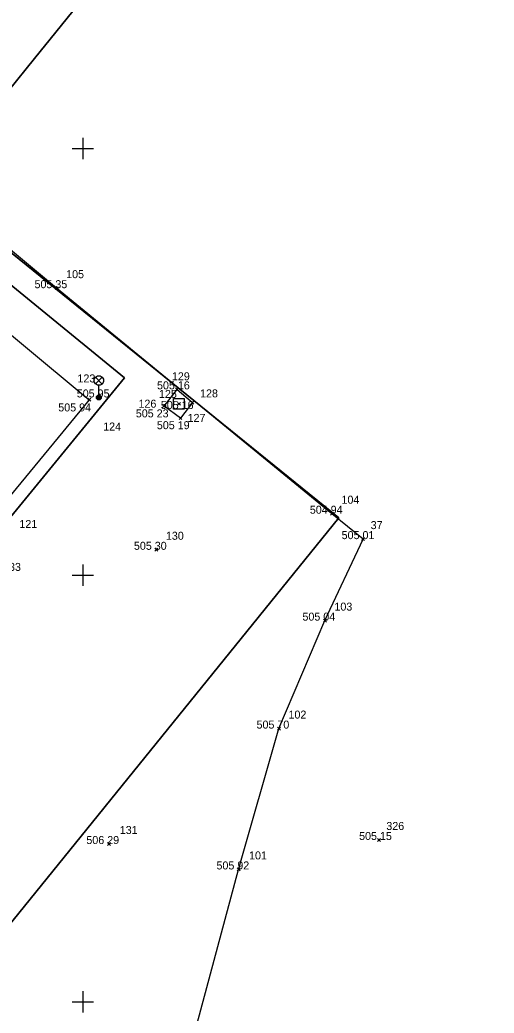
# Model space of a CAD drawing. Extents: x -408550 to -407654, y -1233019 to -1231230.
# Drawn here: x -407922.95 to -407900.75, y -1232060.52 to -1232013.97 of the extents above; entities that cross this region are included whole.
import ezdxf

# ---------------------------------------------------------------- set-up
doc = ezdxf.new("R2010")
doc.units = 0
for name, color, linetype in [('Level 1', 7, 'Continuous'), ('Level 12', 7, 'Continuous'), ('Level 16', 7, 'Continuous'), ('Level 20', 7, 'Continuous'), ('Level 23', 7, 'Continuous'), ('Level 26', 7, 'Continuous'), ('Level 40', 7, 'Continuous'), ('Level 45', 7, 'Continuous')]:
    doc.layers.add(name, color=color, linetype=linetype)

msp = doc.modelspace()

# ---------------------------------------------------------------- linework, layer by layer
at = {"layer": 'Level 1'}
for p, q in [((-407920, -1232019.5), (-407920, -1232020.5)), ((-407920.5, -1232020), (-407919.5, -1232020)), ((-407920, -1232039.5), (-407920, -1232040.5)), ((-407920.5, -1232040), (-407919.5, -1232040)), ((-407920, -1232059.5), (-407920, -1232060.5)), ((-407920.5, -1232060), (-407919.5, -1232060))]:
    msp.add_line(p, q, dxfattribs=at)
for points in [[(-408002.95, -1231959.78), (-407998.58, -1231963.3), (-407985.37, -1231974.5), (-407975.08, -1231982.73), (-407972.21, -1231984.54), (-407969.45, -1231986.76), (-407966.11, -1231989.44), (-407955.64, -1231997.88), (-407939.09, -1232011.47), (-407927.08, -1232021.88), (-407908.02, -1232037.31)], [(-407865.11, -1232098.76), (-407959.41, -1232100.85), (-407908.02, -1232037.31), (-407927.08, -1232021.88), (-407925.98, -1232020.38), (-407922.27, -1232015.79), (-407913.48, -1232004.91), (-407905.89, -1231995.51), (-407896.46, -1231983.85)], [(-407908.02, -1232037.31), (-407959.41, -1232100.85), (-407964.75, -1232098.99), (-407974.67, -1232095.53), (-407985.8, -1232091.65), (-408004.8, -1232085.03), (-408023.96, -1232078.34), (-408035.27, -1232074.4), (-408044.77, -1232071.09)]]:
    msp.add_lwpolyline(points, dxfattribs=at)
for points in [[(-407908.98, -1231973.85), (-407908.6, -1231973.38), (-407908.02, -1231973.41), (-407904.44, -1231976.23), (-407900.26, -1231979.53), (-407895.94, -1231983.2), (-407896.46, -1231983.85), (-407905.89, -1231995.51), (-407913.48, -1232004.91), (-407922.27, -1232015.79), (-407925.98, -1232020.38), (-407927.08, -1232021.88), (-407939.09, -1232011.47)], [(-407945.9, -1232007.95), (-407918.05, -1232030.75), (-407931.35, -1232047), (-407959.2, -1232024.19)], [(-407918.05, -1232030.75), (-407945.9, -1232007.95), (-407959.2, -1232024.19), (-407931.35, -1232047)]]:
    msp.add_lwpolyline(points, close=True, dxfattribs=at)
at = {"layer": 'Level 12'}
msp.add_lwpolyline([(-408056.73, -1232038.31), (-408035.18, -1232049.43), (-408016.67, -1232058.98), (-407995.64, -1232070.23), (-407983.94, -1232082.87), (-407968.55, -1232099.65), (-407955.47, -1232103.17), (-407935.56, -1232108.32), (-407927.78, -1232110.15), (-407922.43, -1232090.45), (-407918.07, -1232073.76), (-407912.71, -1232053.79), (-407910.82, -1232047.19), (-407908.67, -1232042.13), (-407906.88, -1232038.31), (-407908.34, -1232037.12), (-407921.23, -1232026.55), (-407939.09, -1232011.64)], dxfattribs=at)
at = {"layer": 'Level 16'}
for points in [[(-407919.7, -1232031.78), (-407924.37, -1232037.43), (-407923.48, -1232038.26), (-407925.54, -1232040.73), (-407926.5, -1232040), (-407931.46, -1232045.69), (-407956.75, -1232024.26), (-407952.09, -1232018.67), (-407953, -1232017.86), (-407950.95, -1232015.4), (-407949.93, -1232016.06), (-407945.35, -1232010.41)], [(-407914.87, -1232031.91), (-407915.43, -1232032.64), (-407916.2, -1232032.08), (-407915.59, -1232031.29)]]:
    msp.add_lwpolyline(points, close=True, dxfattribs=at)
at = {"layer": 'Level 20'}
msp.add_lwpolyline([(-407915.75, -1232031.72), (-407915.25, -1232031.72), (-407915.25, -1232032.22), (-407915.75, -1232032.22)], close=True, dxfattribs=at)
at = {"layer": 'Level 23'}
for points in [[(-407921.161, -1232026.619), (-407921.299, -1232026.481)], [(-407921.299, -1232026.619), (-407921.161, -1232026.481)], [(-407915.521, -1232031.359), (-407915.659, -1232031.221)], [(-407915.659, -1232031.359), (-407915.521, -1232031.221)], [(-407919.631, -1232031.849), (-407919.769, -1232031.711)], [(-407919.769, -1232031.849), (-407919.631, -1232031.711)], [(-407919.181, -1232031.739), (-407919.319, -1232031.601)], [(-407919.319, -1232031.739), (-407919.181, -1232031.601)], [(-407916.131, -1232032.149), (-407916.269, -1232032.011)], [(-407916.269, -1232032.149), (-407916.131, -1232032.011)], [(-407915.431, -1232032.039), (-407915.569, -1232031.901)], [(-407915.569, -1232032.039), (-407915.431, -1232031.901)], [(-407914.801, -1232031.979), (-407914.939, -1232031.841)], [(-407914.939, -1232031.979), (-407914.801, -1232031.841)], [(-407915.361, -1232032.709), (-407915.499, -1232032.571)], [(-407915.499, -1232032.709), (-407915.361, -1232032.571)], [(-407908.271, -1232037.189), (-407908.409, -1232037.051)], [(-407908.409, -1232037.189), (-407908.271, -1232037.051)], [(-407906.811, -1232038.379), (-407906.949, -1232038.241)], [(-407906.949, -1232038.379), (-407906.811, -1232038.241)], [(-407916.491, -1232038.879), (-407916.629, -1232038.741)], [(-407916.629, -1232038.879), (-407916.491, -1232038.741)], [(-407908.601, -1232042.199), (-407908.739, -1232042.061)], [(-407908.739, -1232042.199), (-407908.601, -1232042.061)], [(-407910.751, -1232047.259), (-407910.889, -1232047.121)], [(-407910.889, -1232047.259), (-407910.751, -1232047.121)], [(-407906.071, -1232052.479), (-407906.209, -1232052.341)], [(-407906.209, -1232052.479), (-407906.071, -1232052.341)], [(-407918.711, -1232052.669), (-407918.849, -1232052.531)], [(-407918.849, -1232052.669), (-407918.711, -1232052.531)], [(-407912.641, -1232053.859), (-407912.779, -1232053.721)], [(-407912.779, -1232053.859), (-407912.641, -1232053.721)]]:
    msp.add_lwpolyline(points, dxfattribs=at)
at = {"layer": 'Level 45'}
for points in [[(-407919.25, -1232031.559), (-407919.25, -1232031.092), (-407919.308, -1232031.092), (-407919.406, -1232031.034), (-407919.467, -1232030.933), (-407919.467, -1232030.817), (-407919.409, -1232030.716), (-407919.308, -1232030.658), (-407919.192, -1232030.658), (-407919.091, -1232030.716), (-407919.033, -1232030.817), (-407919.033, -1232030.933), (-407919.1, -1232031.04), (-407919.192, -1232031.092), (-407919.25, -1232031.092)], [(-407919.1, -1232031.04), (-407919.409, -1232030.716)], [(-407919.406, -1232031.034), (-407919.091, -1232030.716)], [(-407919.25, -1232031.559), (-407919.204, -1232031.559), (-407919.139, -1232031.624), (-407919.139, -1232031.716), (-407919.204, -1232031.781), (-407919.296, -1232031.781), (-407919.361, -1232031.716), (-407919.361, -1232031.624), (-407919.296, -1232031.559), (-407919.25, -1232031.559), (-407919.204, -1232031.571), (-407919.293, -1232031.572), (-407919.31, -1232031.586), (-407919.19, -1232031.586), (-407919.166, -1232031.61), (-407919.334, -1232031.61), (-407919.347, -1232031.634), (-407919.153, -1232031.634), (-407919.153, -1232031.658), (-407919.348, -1232031.659), (-407919.347, -1232031.682), (-407919.152, -1232031.683), (-407919.152, -1232031.706), (-407919.345, -1232031.706), (-407919.334, -1232031.73), (-407919.166, -1232031.73), (-407919.19, -1232031.754), (-407919.31, -1232031.754), (-407919.296, -1232031.767), (-407919.202, -1232031.767)]]:
    msp.add_lwpolyline(points, dxfattribs=at)

# ---------------------------------------------------------------- texts
at = {"layer": 'Level 26'}
for s, p in [('105', (-407920.783, -1232026.08)), ('123', (-407920.253, -1232030.966)), ('129', (-407915.831, -1232030.868)), ('125', (-407916.437, -1232031.693)), ('128', (-407914.513, -1232031.667)), ('126', (-407917.396, -1232032.151)), ('127', (-407915.097, -1232032.817)), ('124', (-407919.048, -1232033.221)), ('104', (-407907.893, -1232036.65)), ('121', (-407922.973, -1232037.79)), ('37', (-407906.526, -1232037.84)), ('130', (-407916.113, -1232038.34)), ('133', (-407923.737, -1232039.8)), ('103', (-407908.223, -1232041.66)), ('102', (-407910.373, -1232046.72)), ('326', (-407905.794, -1232051.94)), ('131', (-407918.273, -1232052.13)), ('101', (-407912.219, -1232053.32))]:
    msp.add_text(s, height=0.375, dxfattribs=at).set_placement(p)
at = {"layer": 'Level 40'}
for s, p in [('505 35', (-407922.264, -1232026.55)), ('505 16', (-407916.528, -1232031.29)), ('505 95', (-407920.285, -1232031.67)), ('505 94', (-407921.151, -1232032.325)), ('505 16', (-407916.351, -1232032.21)), ('505 23', (-407917.521, -1232032.604)), ('505 19', (-407916.536, -1232033.158)), ('504 94', (-407909.375, -1232037.12)), ('505 01', (-407907.886, -1232038.31)), ('505 30', (-407917.61, -1232038.81)), ('505 04', (-407909.72, -1232042.13)), ('505 70', (-407911.87, -1232047.19)), ('505 15', (-407907.068, -1232052.41)), ('506 29', (-407919.836, -1232052.6)), ('505 92', (-407913.745, -1232053.79))]:
    msp.add_text(s, height=0.375, dxfattribs=at).set_placement(p)

doc.saveas('drawing.dxf')
